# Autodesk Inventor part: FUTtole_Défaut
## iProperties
Shininess: 64.0
Length Units: 11269
Angle Units: 11279
Time Units: 11290
Mass Units: 11283
Length Display Precision: 3
Angle Display Precision: 2
Compacted: True
Part Number: FUTtole_Défaut
Document SubType Name: Modeling
Created: 2006-11
Material: Par défaut
Designer: profs_sti
Density: 0.0
Volumn: 0.0
Area: 0.0
PropertySet Name: Model Information
Control State: 0
Master: False
Checked Out: False
Author: profs_sti
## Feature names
1. Base1
